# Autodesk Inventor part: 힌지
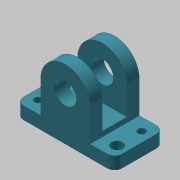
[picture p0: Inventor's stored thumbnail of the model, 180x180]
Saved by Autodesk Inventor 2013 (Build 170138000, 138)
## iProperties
Created: 2019-09
Part Number: 힌지
Material: 알루미늄 6061
Document SubType Name: Modeling
Designer: mduedu
Density: 2.71 g/cm^3
Mass: 20.7756 g
Surface Area: 43.3328 cm^2
Volume: 7.66627 cm^3
Author: mduedu
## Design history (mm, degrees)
sketch "스케치1"
  geometry: L1 (-20, 0)-(20, 0); L2 (20, 0)-(20, 5); L3 (-20, 5)-(-20, 0); L4 (10, 5)-(10, 18); L5 (-10, 18)-(-10, 5); L6 (20, 5)-(10, 5); L7 (-10, 5)-(-20, 5); C1 r 4.5 at (0, 18); A1 r 10 centre (0, 18) between (10, 18) and (-10, 18); 2 further points
  constraints: 14 end point, 4 parallel, 2 centre point, 2 coincident, 2 point on circle, 2 tangent, 1 collinear, 1 horizontal, 1 midpoint, 1 perpendicular, 1 vertical, 1 vertical alignment
  dimensions: "d0" = 40 distance of L1.start L1.end; "d2" = 20 distance between parallel lines of L4 L5; "d3" = 18 distance from line of L1 A1.centre; "d4" = 5 distance of L1.end L2.end; "d5" = 9 diameter of C1
extrude "돌출1" new body sketch "스케치1" stored distance "d6" = 20; taper "d7" = 0 deg
sketch "스케치2"
  geometry: L1 (7, 5)-(37, 5); L2 (37, 5)-(37, -5); L3 (37, -5)-(7, -5); L4 (7, -5)-(7, 5); L5 (0, 10)-(0, -10) reference; 2 further points
  constraints: 8 end point, 2 parallel, 1 horizontal, 1 horizontal alignment, 1 midpoint, 1 perpendicular
  dimensions: "d8" = 7 distance between parallel lines of L5 L4; "d9" = 10 distance of L1.end L2.end; "d10" = 30 distance of L2.end L3.end
extrude "돌출2" cut sketch "스케치2" stored distance "d11" = 20; taper "d12" = 0 deg
sketch "스케치3"
  geometry: 3 further points
  dimensions: "d13" = 16 horizontal distance of point (6, 15) point (-10, 10); "d14" = 32 horizontal distance of point (-26, 5) point (6, 15); "d15" = 5 vertical distance of point (6, 15) point (-10, 10); "d16" = 10 vertical distance of point (-26, 5) point (6, 15)
hole "구멍1" sketch "스케치3" at (6, 15), (-26, 5) diameter "d17" = 3; stored, may be unused: countersink angle "d21" = 90 deg, drill point angle "d23" = 118 deg; dims "d18" = 6, "d19" = 4, "d20" = 2, "d22" = 8
sketch "스케치4"
  geometry: C1 r 1.5 at (6, 15) reference; C2 r 1.5 at (-26, 5) reference; 3 further points
  constraints: 2 horizontal alignment, 2 vertical alignment
hole "구멍2" sketch "스케치4" at (-26, 15), (6, 5) diameter "d24" = 4.5; stored, may be unused: countersink angle "d28" = 90 deg, drill point angle "d30" = 118 deg; dims "d25" = 6, "d26" = 4, "d27" = 2, "d29" = 8
fillet "모깎기1" dims "d31" = 3
node "솔리드1"
